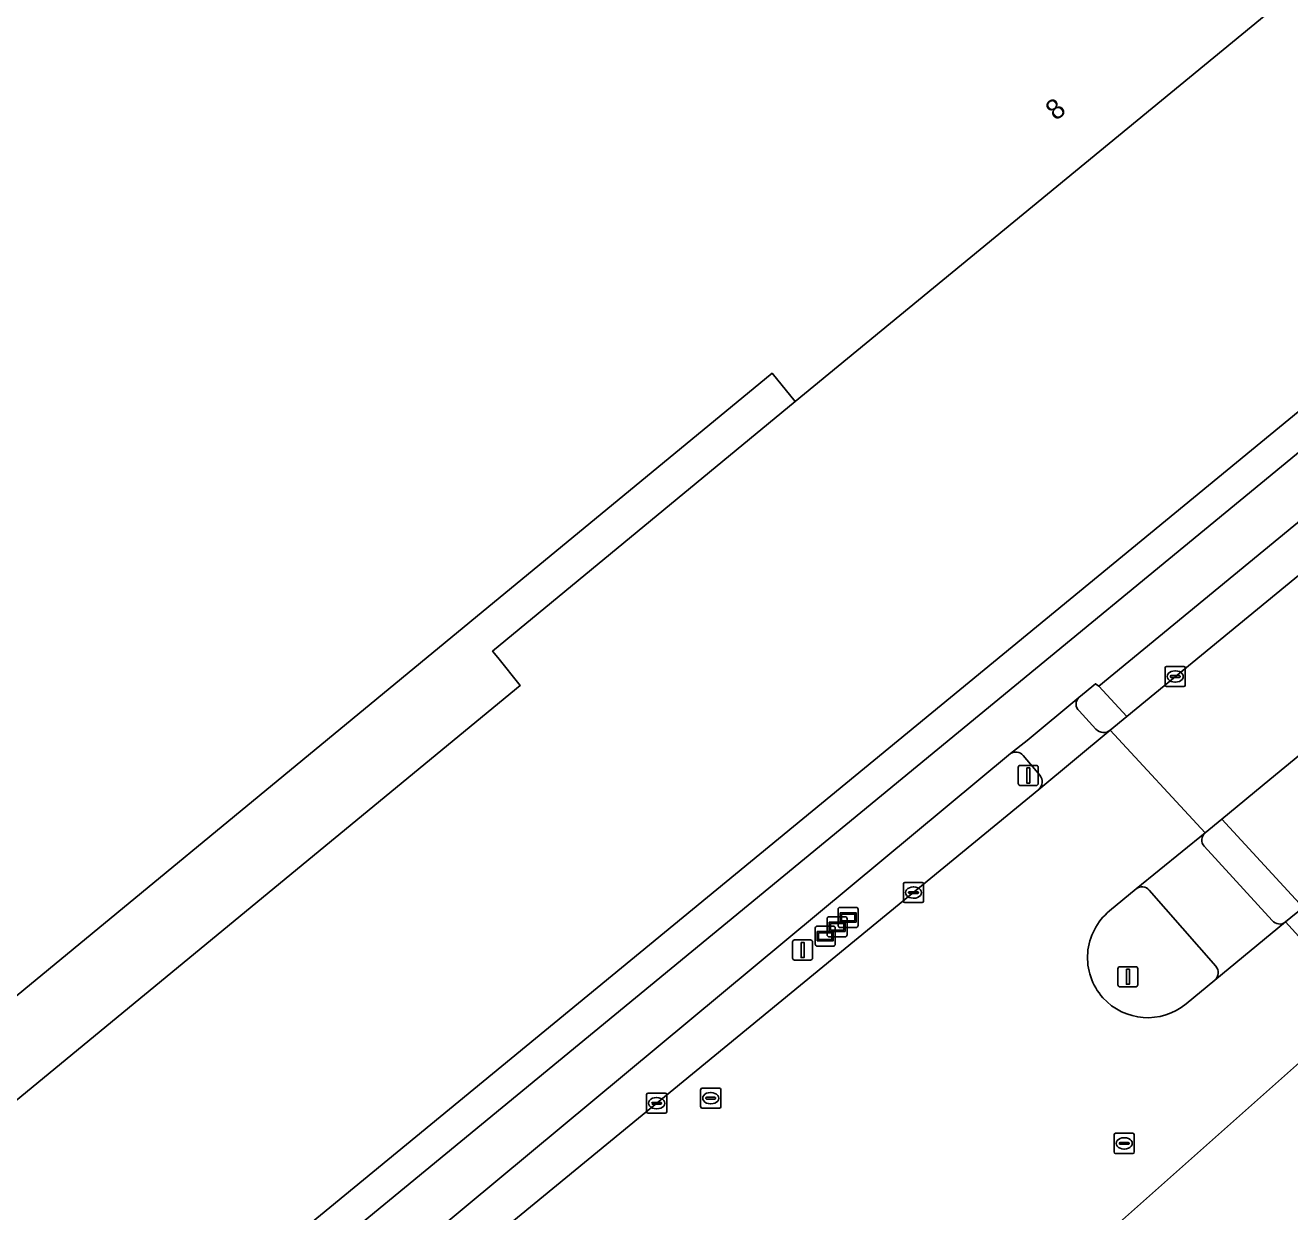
# Model space of a CAD drawing. Extents: x 156141 to 158132, y 385651 to 388333.
# Drawn here: x 157144.8 to 157207.6, y 386419.6 to 386478.5 of the extents above; entities that cross this region are included whole.
import ezdxf

# ---------------------------------------------------------------- set-up
doc = ezdxf.new("R2010")
doc.units = 0
for name, color, linetype in [('IMGEO_Berm_groen', 7, 'Continuous'), ('IMGEO_Erf', 7, 'Continuous'), ('IMGEO_Fietspad_gesloten', 7, 'Continuous'), ('IMGEO_Fietspad_open', 7, 'Continuous'), ('IMGEO_Kolk', 7, 'Continuous'), ('IMGEO_Lichtmast', 7, 'Continuous'), ('IMGEO_Pand', 7, 'Continuous'), ('IMGEO_Pand_nummerreeks', 7, 'Continuous'), ('IMGEO_Pand_overbouw', 7, 'Continuous'), ('IMGEO_Rijbaan_lokaal_gesloten', 7, 'Continuous'), ('IMGEO_Rioolput', 7, 'Continuous'), ('IMGEO_Verkeersbordpaal', 7, 'Continuous'), ('IMGEO_Verkeerseiland_gesloten', 7, 'Continuous'), ('IMGEO_Voetpad_open', 7, 'Continuous'), ('IMGEO_Wegwijzer', 7, 'Continuous')]:
    doc.layers.add(name, color=color, linetype=linetype)

msp = doc.modelspace()

# ---------------------------------------------------------------- linework, layer by layer
at = {"layer": 'IMGEO_Berm_groen'}
for points in [[(157300.316, 386520.754), (157297.333, 386518.166), (157296.237, 386517.167), (157295.124, 386516.068), (157282.268, 386503.453), (157281.172, 386502.46), (157280.036, 386501.455), (157278.267, 386500), (157243.651, 386471.523), (157206.577, 386441.019), (157204.194, 386439.055), (157208.222, 386434.667), (157210.644, 386436.639), (157221.285, 386445.357)], [(157193.703, 386442.312), (157155.467, 386410.521)], [(157195.153, 386441.233), (157194.329, 386442.218)], [(157155.626, 386407.901), (157165.281, 386416.006), (157167.841, 386418.13), (157195.098, 386440.53)]]:
    msp.add_lwpolyline(points, dxfattribs=at)
msp.add_lwpolyline([(157218.742, 386459.988), (157217.434, 386461.573), (157198.088, 386445.659), (157199.479, 386444.152)], close=True, dxfattribs=at)
for centre, radius, start, end in [((157193.96, 386441.889), 0.494, 41.64877, 121.2718), ((157194.749, 386440.911), 0.517, 312.52243, 38.5306)]:
    msp.add_arc(centre, radius, start, end, dxfattribs=at)
at = {"layer": 'IMGEO_Erf'}
msp.add_lwpolyline([(157116.212, 386500), (157127.098, 386508.962), (157133.365, 386514.121), (157165.777, 386540.804), (157199.375, 386500), (157212.507, 386484.051), (157183.012, 386459.796), (157181.862, 386461.196), (157166.855, 386448.839), (157138.856, 386425.768), (157126.754, 386415.792), (157110.039, 386436.118), (157108.665, 386434.944), (157079.786, 386470.013)], close=True, dxfattribs=at)
msp.add_lwpolyline([(157143.102, 386405.97), (157215.589, 386465.536), (157216.06, 386465.946), (157224.126, 386472.581), (157224.923, 386473.224), (157226.605, 386474.613), (157213.099, 386491.073)], dxfattribs=at)
at = {"layer": 'IMGEO_Fietspad_gesloten'}
for points in [[(157264.038, 386500), (157296.442, 386526.682), (157381.274, 386596.535), (157379.639, 386598.545), (157294.792, 386528.687), (157259.949, 386500), (157236.74, 386480.891), (157225.904, 386471.963), (157216.572, 386464.306), (157144.792, 386405.245)], [(157145.071, 386402.056), (157149.786, 386405.826), (157155.467, 386410.521), (157193.703, 386442.312), (157194.517, 386442.962), (157197.093, 386445.093), (157197.92, 386445.771), (157198.088, 386445.659), (157217.434, 386461.573), (157228.213, 386470.509), (157228.313, 386470.591), (157234.595, 386475.759), (157238.172, 386478.701), (157264.038, 386500)]]:
    msp.add_lwpolyline(points, dxfattribs=at)
at = {"layer": 'IMGEO_Fietspad_open'}
for points in [[(157197.093, 386445.093), (157194.517, 386442.962), (157193.703, 386442.312)], [(157197.94, 386443.515), (157197.098, 386444.428)], [(157195.098, 386440.53), (157198.65, 386443.469)], [(157194.329, 386442.218), (157195.153, 386441.233)], [(157203.359, 386438.368), (157199.931, 386435.593)], [(157206.683, 386434.017), (157203.31, 386437.708)], [(157200.587, 386435.526), (157203.886, 386431.756)], [(157203.837, 386431.054), (157207.355, 386433.947)]]:
    msp.add_lwpolyline(points, dxfattribs=at)
for centre, radius, start, end in [((157197.4, 386444.763), 0.451, 132.87315, 227.98843), ((157198.32, 386443.872), 0.521, 223.24913, 309.33699), ((157193.96, 386441.889), 0.494, 41.64877, 121.2718), ((157194.749, 386440.911), 0.517, 312.52243, 38.5306), ((157203.649, 386438.015), 0.457, 129.34674, 222.16128), ((157200.221, 386435.186), 0.5, 42.89121, 125.44552), ((157207.055, 386434.326), 0.483, 219.69609, 308.41018), ((157203.524, 386431.429), 0.488, 309.87467, 42.13972)]:
    msp.add_arc(centre, radius, start, end, dxfattribs=at)
at = {"layer": 'IMGEO_Kolk'}
for p, q in [((157201.373, 386445.709), (157201.373, 386446.561)), ((157201.448, 386446.635), (157202.3, 386446.635)), ((157202.374, 386446.561), (157202.374, 386445.709)), ((157201.632, 386446.129), (157201.632, 386446.141)), ((157202.07, 386446.092), (157201.672, 386446.092)), ((157201.675, 386446.178), (157202.073, 386446.178)), ((157201.861, 386446.415), (157201.886, 386446.415)), ((157202.116, 386446.141), (157202.116, 386446.129)), ((157202.3, 386445.635), (157201.448, 386445.635)), ((157201.884, 386445.855), (157201.859, 386445.855)), ((157188.381, 386434.98), (157188.381, 386435.832)), ((157188.456, 386435.906), (157189.308, 386435.906)), ((157189.382, 386435.832), (157189.382, 386434.98)), ((157188.64, 386435.4), (157188.64, 386435.412)), ((157189.078, 386435.363), (157188.68, 386435.363)), ((157188.683, 386435.449), (157189.081, 386435.449)), ((157188.869, 386435.686), (157188.894, 386435.686)), ((157189.124, 386435.412), (157189.124, 386435.4)), ((157189.308, 386434.906), (157188.456, 386434.906)), ((157188.892, 386435.126), (157188.867, 386435.126)), ((157175.632, 386424.521), (157175.632, 386425.373)), ((157175.707, 386425.447), (157176.559, 386425.447)), ((157176.12, 386425.227), (157176.145, 386425.227)), ((157176.633, 386425.373), (157176.633, 386424.521)), ((157175.891, 386424.941), (157175.891, 386424.953)), ((157176.329, 386424.904), (157175.931, 386424.904)), ((157175.934, 386424.99), (157176.332, 386424.99)), ((157176.143, 386424.667), (157176.118, 386424.667)), ((157176.375, 386424.953), (157176.375, 386424.941)), ((157176.559, 386424.447), (157175.707, 386424.447))]:
    msp.add_line(p, q, dxfattribs=at)
for points in [[(157201.373, 386445.709), (157201.373, 386446.561)], [(157201.448, 386446.635), (157202.3, 386446.635)], [(157202.374, 386446.561), (157202.374, 386445.709)], [(157202.3, 386445.635), (157201.448, 386445.635)], [(157188.381, 386434.98), (157188.381, 386435.832)], [(157188.456, 386435.906), (157189.308, 386435.906)], [(157189.382, 386435.832), (157189.382, 386434.98)], [(157189.308, 386434.906), (157188.456, 386434.906)], [(157175.632, 386424.521), (157175.632, 386425.373)], [(157175.707, 386425.447), (157176.559, 386425.447)], [(157176.633, 386425.373), (157176.633, 386424.521)], [(157176.559, 386424.447), (157175.707, 386424.447)]]:
    msp.add_lwpolyline(points, dxfattribs=at)
for centre, radius, start, end in [((157201.45, 386446.559), 0.0765, 91.55205, 178.44795), ((157201.45, 386446.559), 0.0765, 91.55205, 178.44795), ((157202.298, 386446.559), 0.0765, 1.55205, 88.44795), ((157202.298, 386446.559), 0.0765, 1.55205, 88.44795), ((157201.672, 386446.138), 0.0403, 85.87752, 175.75265), ((157201.669, 386446.128), 0.0366, 178.93798, 274.71019), ((157202.073, 386446.135), 0.043, 264.86636, 352.45326), ((157202.077, 386446.14), 0.0386, 1.73085, 96.63898), ((157201.45, 386445.711), 0.0765, 181.55205, 268.44795), ((157201.45, 386445.711), 0.0765, 181.55205, 268.44795), ((157202.298, 386445.711), 0.0765, 271.55205, 358.44795), ((157202.298, 386445.711), 0.0765, 271.55205, 358.44795), ((157188.458, 386435.83), 0.0765, 91.55205, 178.44795), ((157188.458, 386435.83), 0.0765, 91.55205, 178.44795), ((157189.306, 386435.83), 0.0765, 1.55205, 88.44795), ((157189.306, 386435.83), 0.0765, 1.55205, 88.44795), ((157188.68, 386435.409), 0.0403, 85.87752, 175.75265), ((157188.677, 386435.399), 0.0366, 178.93798, 274.71019), ((157189.081, 386435.406), 0.043, 264.86636, 352.45326), ((157189.085, 386435.411), 0.0386, 1.73085, 96.63898), ((157188.458, 386434.982), 0.0765, 181.55205, 268.44795), ((157188.458, 386434.982), 0.0765, 181.55205, 268.44795), ((157189.306, 386434.982), 0.0765, 271.55205, 358.44795), ((157189.306, 386434.982), 0.0765, 271.55205, 358.44795), ((157175.709, 386425.371), 0.0765, 91.55205, 178.44795), ((157175.709, 386425.371), 0.0765, 91.55205, 178.44795), ((157176.557, 386425.371), 0.0765, 1.55205, 88.44795), ((157176.557, 386425.371), 0.0765, 1.55205, 88.44795), ((157175.931, 386424.95), 0.0403, 85.87752, 175.75265), ((157175.928, 386424.94), 0.0366, 178.93798, 274.71019), ((157176.332, 386424.947), 0.043, 264.86636, 352.45326), ((157176.336, 386424.952), 0.0386, 1.73085, 96.63898), ((157175.709, 386424.523), 0.0765, 181.55205, 268.44795), ((157175.709, 386424.523), 0.0765, 181.55205, 268.44795), ((157176.557, 386424.523), 0.0765, 271.55205, 358.44795), ((157176.557, 386424.523), 0.0765, 271.55205, 358.44795)]:
    msp.add_arc(centre, radius, start, end, dxfattribs=at)
for centre, major_axis, ratio, start_param, end_param in [((157201.86, 386446.135), (-0.387, 0.002), 0.722429, 4.712389, 7.853982), ((157201.885, 386446.135), (-0.39, 0.002), 0.717154, 1.570796, 4.712389), ((157188.868, 386435.406), (-0.387, 0.002), 0.722429, 4.712389, 7.853982), ((157188.893, 386435.406), (-0.39, 0.002), 0.717154, 1.570796, 4.712389), ((157176.119, 386424.947), (-0.387, 0.002), 0.722429, 4.712389, 7.853982), ((157176.144, 386424.947), (-0.39, 0.002), 0.717154, 1.570796, 4.712389)]:
    msp.add_ellipse(centre, major_axis=major_axis, ratio=ratio, start_param=start_param, end_param=end_param, dxfattribs=at)
at = {"layer": 'IMGEO_Lichtmast'}
for p, q in [((157199.027, 386430.825), (157199.027, 386431.625)), ((157199.027, 386431.625), (157199.027, 386430.825)), ((157199.127, 386431.725), (157199.917, 386431.725)), ((157199.917, 386431.725), (157199.127, 386431.725)), ((157200.017, 386431.625), (157200.017, 386430.825)), ((157200.017, 386430.825), (157200.017, 386431.625)), ((157199.917, 386430.725), (157199.127, 386430.725)), ((157199.127, 386430.725), (157199.917, 386430.725))]:
    msp.add_line(p, q, dxfattribs=at)
msp.add_lwpolyline([(157199.447, 386431.6), (157199.597, 386431.6), (157199.597, 386430.85), (157199.447, 386430.85), (157199.447, 386431.6)], dxfattribs=at)
for centre, start, end in [((157199.127, 386431.625), 90, 180), ((157199.127, 386431.625), 90, 180), ((157199.917, 386431.625), 0, 90), ((157199.917, 386431.625), 360, 90), ((157199.127, 386430.825), 180, 270), ((157199.127, 386430.825), 180, 270), ((157199.917, 386430.825), 270, 0), ((157199.917, 386430.825), 270, 0)]:
    msp.add_arc(centre, 0.1, start, end, dxfattribs=at)
at = {"layer": 'IMGEO_Pand'}
msp.add_lwpolyline([(157183.012, 386459.796), (157212.507, 386484.051), (157199.375, 386500), (157165.777, 386540.804), (157133.365, 386514.121), (157127.098, 386508.962), (157116.212, 386500), (157079.786, 386470.013), (157108.665, 386434.944), (157110.039, 386436.118), (157126.754, 386415.792), (157138.856, 386425.768), (157166.855, 386448.839), (157181.862, 386461.196)], close=True, dxfattribs=at)
at = {"layer": 'IMGEO_Pand_overbouw'}
msp.add_lwpolyline([(157108.665, 386434.944), (157126.515, 386413.267), (157139.993, 386424.367), (157141.385, 386422.655), (157141.518, 386422.764), (157169.359, 386445.693), (157168.245, 386447.074), (157167.989, 386447.391), (157183.012, 386459.796), (157181.862, 386461.196), (157166.855, 386448.839), (157138.856, 386425.768), (157126.754, 386415.792), (157110.039, 386436.118)], close=True, dxfattribs=at)
at = {"layer": 'IMGEO_Rijbaan_lokaal_gesloten'}
for points in [[(157267.318, 386500), (157239.52, 386477.108), (157235.943, 386474.164), (157229.635, 386468.971), (157229.533, 386468.887), (157218.742, 386459.988), (157199.479, 386444.152), (157198.65, 386443.469), (157203.359, 386438.368), (157204.194, 386439.055), (157206.577, 386441.019), (157243.651, 386471.523), (157278.267, 386500)], [(157221.285, 386445.357), (157210.644, 386436.639), (157208.222, 386434.667), (157207.355, 386433.947), (157211.163, 386429.749), (157211.89, 386430.761)], [(157198.617, 386434.493), (157199.931, 386435.593), (157203.359, 386438.368), (157198.65, 386443.469), (157195.098, 386440.53), (157167.841, 386418.13), (157172.303, 386412.729), (157172.509, 386412.896), (157176.417, 386416.128)], [(157211.163, 386429.749), (157207.355, 386433.947), (157203.837, 386431.054), (157202.415, 386429.885)], [(157180.048, 386411.402), (157176.43, 386408.415), (157176.215, 386408.236), (157181.072, 386402.975), (157195.384, 386415.709), (157211.163, 386429.749)], [(157211.163, 386429.749), (157195.384, 386415.709), (157196.727, 386414.083)]]:
    msp.add_lwpolyline(points, dxfattribs=at)
for centre, start, end in [((157200.504, 386432.18), 129.21271, 221.94716), ((157200.505, 386432.179), 221.91869, 309.77407)]:
    msp.add_arc(centre, 2.985, start, end, dxfattribs=at)
at = {"layer": 'IMGEO_Rioolput'}
for p, q in [((157178.317, 386424.77), (157178.317, 386425.622)), ((157178.392, 386425.696), (157179.244, 386425.696)), ((157178.576, 386425.19), (157178.576, 386425.202)), ((157178.619, 386425.239), (157179.017, 386425.239)), ((157178.805, 386425.476), (157178.83, 386425.476)), ((157179.06, 386425.202), (157179.06, 386425.19)), ((157179.318, 386425.622), (157179.318, 386424.77)), ((157179.244, 386424.696), (157178.392, 386424.696)), ((157179.014, 386425.153), (157178.616, 386425.153)), ((157178.828, 386424.916), (157178.803, 386424.916)), ((157198.841, 386422.526), (157198.841, 386423.378)), ((157198.916, 386423.452), (157199.768, 386423.452)), ((157199.842, 386423.378), (157199.842, 386422.526)), ((157199.1, 386422.946), (157199.1, 386422.958)), ((157199.538, 386422.909), (157199.14, 386422.909)), ((157199.143, 386422.995), (157199.541, 386422.995)), ((157199.352, 386422.672), (157199.327, 386422.672)), ((157199.329, 386423.232), (157199.354, 386423.232)), ((157199.584, 386422.958), (157199.584, 386422.946)), ((157199.768, 386422.452), (157198.916, 386422.452))]:
    msp.add_line(p, q, dxfattribs=at)
for points in [[(157178.317, 386424.77), (157178.317, 386425.622)], [(157178.392, 386425.696), (157179.244, 386425.696)], [(157179.318, 386425.622), (157179.318, 386424.77)], [(157179.244, 386424.696), (157178.392, 386424.696)], [(157198.841, 386422.526), (157198.841, 386423.378)], [(157198.916, 386423.452), (157199.768, 386423.452)], [(157199.842, 386423.378), (157199.842, 386422.526)], [(157199.768, 386422.452), (157198.916, 386422.452)]]:
    msp.add_lwpolyline(points, dxfattribs=at)
for centre, radius, start, end in [((157178.394, 386425.62), 0.0765, 91.55205, 178.44795), ((157178.394, 386425.62), 0.0765, 91.55205, 178.44795), ((157178.616, 386425.199), 0.0403, 85.87752, 175.75265), ((157178.613, 386425.189), 0.0366, 178.93798, 274.71019), ((157179.017, 386425.196), 0.043, 264.86636, 352.45326), ((157179.021, 386425.201), 0.0386, 1.73085, 96.63898), ((157179.242, 386425.62), 0.0765, 1.55205, 88.44795), ((157179.242, 386425.62), 0.0765, 1.55205, 88.44795), ((157178.394, 386424.772), 0.0765, 181.55205, 268.44795), ((157178.394, 386424.772), 0.0765, 181.55205, 268.44795), ((157179.242, 386424.772), 0.0765, 271.55205, 358.44795), ((157179.242, 386424.772), 0.0765, 271.55205, 358.44795), ((157198.918, 386423.376), 0.0765, 91.55205, 178.44795), ((157198.918, 386423.376), 0.0765, 91.55205, 178.44795), ((157199.766, 386423.376), 0.0765, 1.55205, 88.44795), ((157199.766, 386423.376), 0.0765, 1.55205, 88.44795), ((157199.14, 386422.955), 0.0403, 85.87752, 175.75265), ((157199.137, 386422.945), 0.0366, 178.93798, 274.71019), ((157199.541, 386422.952), 0.043, 264.86636, 352.45326), ((157199.545, 386422.957), 0.0386, 1.73085, 96.63898), ((157198.918, 386422.528), 0.0765, 181.55205, 268.44795), ((157198.918, 386422.528), 0.0765, 181.55205, 268.44795), ((157199.766, 386422.528), 0.0765, 271.55205, 358.44795), ((157199.766, 386422.528), 0.0765, 271.55205, 358.44795)]:
    msp.add_arc(centre, radius, start, end, dxfattribs=at)
for centre, major_axis, ratio, start_param, end_param in [((157178.804, 386425.196), (-0.387, 0.002), 0.722429, 4.712389, 7.853982), ((157178.829, 386425.196), (-0.39, 0.002), 0.717154, 1.570796, 4.712389), ((157199.328, 386422.952), (-0.387, 0.002), 0.722429, 4.712389, 7.853982), ((157199.353, 386422.952), (-0.39, 0.002), 0.717154, 1.570796, 4.712389)]:
    msp.add_ellipse(centre, major_axis=major_axis, ratio=ratio, start_param=start_param, end_param=end_param, dxfattribs=at)
at = {"layer": 'IMGEO_Verkeersbordpaal'}
for p, q in [((157194.083, 386440.821), (157194.083, 386441.621)), ((157194.083, 386441.621), (157194.083, 386440.821)), ((157194.183, 386441.721), (157194.973, 386441.721)), ((157194.973, 386441.721), (157194.183, 386441.721)), ((157195.073, 386441.621), (157195.073, 386440.821)), ((157195.073, 386440.821), (157195.073, 386441.621)), ((157194.973, 386440.721), (157194.183, 386440.721)), ((157194.183, 386440.721), (157194.973, 386440.721)), ((157182.878, 386432.154), (157182.878, 386432.954)), ((157182.878, 386432.954), (157182.878, 386432.154)), ((157182.978, 386433.054), (157183.768, 386433.054)), ((157183.768, 386433.054), (157182.978, 386433.054)), ((157183.868, 386432.954), (157183.868, 386432.154)), ((157183.868, 386432.154), (157183.868, 386432.954)), ((157183.768, 386432.054), (157182.978, 386432.054)), ((157182.978, 386432.054), (157183.768, 386432.054))]:
    msp.add_line(p, q, dxfattribs=at)
for points in [[(157194.503, 386441.596), (157194.653, 386441.596), (157194.653, 386440.846), (157194.503, 386440.846), (157194.503, 386441.596)], [(157183.298, 386432.929), (157183.448, 386432.929), (157183.448, 386432.179), (157183.298, 386432.179), (157183.298, 386432.929)]]:
    msp.add_lwpolyline(points, dxfattribs=at)
for centre, start, end in [((157194.183, 386441.621), 90, 180), ((157194.183, 386441.621), 90, 180), ((157194.973, 386441.621), 0, 90), ((157194.973, 386441.621), 360, 90), ((157194.183, 386440.821), 180, 270), ((157194.183, 386440.821), 180, 270), ((157194.973, 386440.821), 270, 0), ((157194.973, 386440.821), 270, 0), ((157182.978, 386432.954), 90, 180), ((157182.978, 386432.954), 90, 180), ((157183.768, 386432.954), 0, 90), ((157183.768, 386432.954), 360, 90), ((157182.978, 386432.154), 180, 270), ((157182.978, 386432.154), 180, 270), ((157183.768, 386432.154), 270, 0), ((157183.768, 386432.154), 270, 0)]:
    msp.add_arc(centre, 0.1, start, end, dxfattribs=at)
at = {"layer": 'IMGEO_Verkeerseiland_gesloten'}
for points in [[(157199.931, 386435.593), (157198.617, 386434.493)], [(157203.886, 386431.756), (157200.587, 386435.526)], [(157202.415, 386429.885), (157203.837, 386431.054)]]:
    msp.add_lwpolyline(points, dxfattribs=at)
for centre, radius, start, end in [((157200.221, 386435.186), 0.5, 42.89121, 125.44552), ((157200.504, 386432.18), 2.985, 129.21271, 221.94716), ((157203.524, 386431.429), 0.488, 309.87467, 42.13972), ((157200.505, 386432.179), 2.985, 221.91869, 309.77407)]:
    msp.add_arc(centre, radius, start, end, dxfattribs=at)
at = {"layer": 'IMGEO_Voetpad_open'}
for points in [[(157144.792, 386405.245), (157216.572, 386464.306), (157215.589, 386465.536), (157143.102, 386405.97)], [(157198.65, 386443.469), (157199.479, 386444.152), (157198.088, 386445.659), (157197.92, 386445.771), (157197.093, 386445.093)], [(157197.098, 386444.428), (157197.94, 386443.515)], [(157207.355, 386433.947), (157208.222, 386434.667), (157204.194, 386439.055), (157203.359, 386438.368)], [(157203.31, 386437.708), (157206.683, 386434.017)]]:
    msp.add_lwpolyline(points, dxfattribs=at)
for centre, radius, start, end in [((157197.4, 386444.763), 0.451, 132.87315, 227.98843), ((157198.32, 386443.872), 0.521, 223.24913, 309.33699), ((157203.649, 386438.015), 0.457, 129.34674, 222.16128), ((157207.055, 386434.326), 0.483, 219.69609, 308.41018)]:
    msp.add_arc(centre, radius, start, end, dxfattribs=at)
at = {"layer": 'IMGEO_Wegwijzer'}
for p, q in [((157185.139, 386433.77), (157185.139, 386434.57)), ((157185.139, 386434.57), (157185.139, 386433.77)), ((157185.239, 386434.67), (157186.029, 386434.67)), ((157186.029, 386434.67), (157185.239, 386434.67)), ((157186.129, 386434.57), (157186.129, 386433.77)), ((157186.129, 386433.77), (157186.129, 386434.57)), ((157184.596, 386433.307), (157184.596, 386434.107)), ((157184.596, 386434.107), (157184.596, 386433.307)), ((157184.696, 386434.207), (157185.486, 386434.207)), ((157185.486, 386434.207), (157184.696, 386434.207)), ((157185.586, 386434.107), (157185.586, 386433.307)), ((157185.586, 386433.307), (157185.586, 386434.107)), ((157184.007, 386432.842), (157184.007, 386433.642)), ((157184.007, 386433.642), (157184.007, 386432.842)), ((157184.107, 386433.742), (157184.897, 386433.742)), ((157184.897, 386433.742), (157184.107, 386433.742)), ((157184.997, 386433.642), (157184.997, 386432.842)), ((157184.997, 386432.842), (157184.997, 386433.642)), ((157186.029, 386433.67), (157185.239, 386433.67)), ((157185.239, 386433.67), (157186.029, 386433.67)), ((157184.897, 386432.742), (157184.107, 386432.742)), ((157184.107, 386432.742), (157184.897, 386432.742)), ((157185.486, 386433.207), (157184.696, 386433.207)), ((157184.696, 386433.207), (157185.486, 386433.207))]:
    msp.add_line(p, q, dxfattribs=at)
for points in [[(157185.24, 386434.402), (157186.028, 386434.402), (157186.028, 386433.938), (157185.24, 386433.938), (157185.24, 386434.402)], [(157185.305, 386434.337), (157185.305, 386434.003), (157185.963, 386434.003), (157185.963, 386434.337), (157185.305, 386434.337)], [(157184.108, 386433.474), (157184.896, 386433.474), (157184.896, 386433.01), (157184.108, 386433.01), (157184.108, 386433.474)], [(157184.173, 386433.409), (157184.173, 386433.075), (157184.831, 386433.075), (157184.831, 386433.409), (157184.173, 386433.409)], [(157184.697, 386433.939), (157185.485, 386433.939), (157185.485, 386433.475), (157184.697, 386433.475), (157184.697, 386433.939)], [(157184.762, 386433.874), (157184.762, 386433.54), (157185.42, 386433.54), (157185.42, 386433.874), (157184.762, 386433.874)]]:
    msp.add_lwpolyline(points, dxfattribs=at)
for centre, start, end in [((157185.239, 386434.57), 90, 180), ((157185.239, 386434.57), 90, 180), ((157186.029, 386434.57), 0, 90), ((157186.029, 386434.57), 360, 90), ((157184.696, 386434.107), 90, 180), ((157184.696, 386434.107), 90, 180), ((157185.486, 386434.107), 0, 90), ((157185.486, 386434.107), 360, 90), ((157184.107, 386433.642), 90, 180), ((157184.107, 386433.642), 90, 180), ((157184.897, 386433.642), 0, 90), ((157184.897, 386433.642), 360, 90), ((157185.239, 386433.77), 180, 270), ((157185.239, 386433.77), 180, 270), ((157186.029, 386433.77), 270, 0), ((157186.029, 386433.77), 270, 0), ((157184.107, 386432.842), 180, 270), ((157184.107, 386432.842), 180, 270), ((157184.696, 386433.307), 180, 270), ((157184.696, 386433.307), 180, 270), ((157184.897, 386432.842), 270, 0), ((157184.897, 386432.842), 270, 0), ((157185.486, 386433.307), 270, 0), ((157185.486, 386433.307), 270, 0)]:
    msp.add_arc(centre, 0.1, start, end, dxfattribs=at)

# ---------------------------------------------------------------- texts
at = {"layer": 'IMGEO_Pand_nummerreeks'}
msp.add_text('8', height=1, rotation=39.43192, dxfattribs=at).set_placement((157195.95, 386473.697))

doc.saveas('drawing.dxf')
